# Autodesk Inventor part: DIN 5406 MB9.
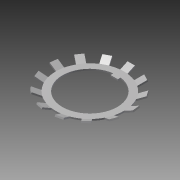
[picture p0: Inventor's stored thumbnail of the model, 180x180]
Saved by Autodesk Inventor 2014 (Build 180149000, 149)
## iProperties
Created: 2001-02
Part Number: DIN 5406 MB9.
Material: Steel, Mild
Description: Lockwasher DIN 5406 MB9.
Document SubType Name: Modeling
Standard: DIN 5406
Density: 7.86 g/cm^3
Appearance: Steel
ProtocolID: P00020917134434882
Protocol: P00020917134434882<@PID>[Version]<@EL>Version=2.2<@EL>[Synchronize]<@EL>ChangedVars=<@EL>[Main]<@EL>View=MODEL<@EL>DataFile=SpiData|D5406<@EL>Standard=DIN<@EL>P
Control State: 0
Master: False
Checked Out: False
Shininess: 20.0
Length Units: 11269
Angle Units: 11279
Time Units: 11290
Mass Units: 11283
Length Display Precision: 4
Angle Display Precision: 4
BOM1: Lockwasher
BOM2: MB9
BOM3: DIN 5406
Density: 7.86
Volumn: 0.16769280051275087
Area: 5.389621106468172
PropertySet Name: Model Information
Author: PaulN
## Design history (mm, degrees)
sketch "Sketch3"
  geometry: L1 (0, 0)-(0, 22.5); L2 (-3, 22.299)-(-3, 20); L3 (3, 22.299)-(3, 20); L4 (-3, 20)-(3, 20); C1 r 28 at (0, 0); A1 r 22.5 centre (0, 0) between (-3, 22.299) and (3, 22.299)
  constraints: 8 end point, 3 point on circle, 2 centre point, 2 symmetric about line, 1 coincident, 1 parallel, 1 perpendicular, 1 vertical, 2 other
  dimensions: "d7" = 45 diameter of A1 (= prf_ds); "d8" = 56 diameter of C1 (= prf_d1); "d39" = 6 distance of L2.end L3.end (= prf_f); "d40" = 42.5 dimension on A1 L4 (= prf_M)
extrude "Extrusion1" new body sketch "Sketch3" distance "d9" = 1.25 (= prf_B); taper "d10" = 0 deg
sketch "Sketch6"
  geometry: L1 (28, 0)-(28, 1.25) reference; L2 (28, 1.25)-(33.972, 4.035); L3 (33.972, 4.035)-(34.5, 2.902); L4 (34.5, 2.902)-(28.277, 0); L5 (28.277, 0)-(22.5, 0); L6 (22.5, 0)-(22.5, 1.25); L7 (22.5, 1.25)-(28, 1.25); L8 (0, -0.807)-(0, 4.842) reference
  constraints: 12 end point, 3 perpendicular, 2 parallel, 1 horizontal alignment
  dimensions: "d41" = 1.25 distance between parallel lines of L2 L4 (= prf_B); "d42" = 45 diameter of L6 L8 (= prf_ds); "d43" = 69 diameter of L3.end L8 (= prf_d3); "d44" = 25 deg angle of L4 L5
extrude "Extrusion2" join sketch "Sketch6" stored distance "d45" = 6 (= prf_t); taper "d46" = 0 deg
pattern_circular "Circular Pattern2" dims angle "d49" = 360 deg
body "Solid1"
other parameters: "prf_ds" = 45 [user parameter; used in 2 equation terms], "prf_d1" = 56 [user parameter; used in 1 equation term], "prf_d3" = 69 [user parameter; used in 1 equation term], "prf_f" = 6 [user parameter; used in 1 equation term], "prf_M" = 42.5 [user parameter; used in 1 equation term], "prf_B" = 1.25 [user parameter; used in 2 equation terms], "prf_t" = 6 [user parameter; used in 1 equation term], "d50" = 0, "d51" = 0
